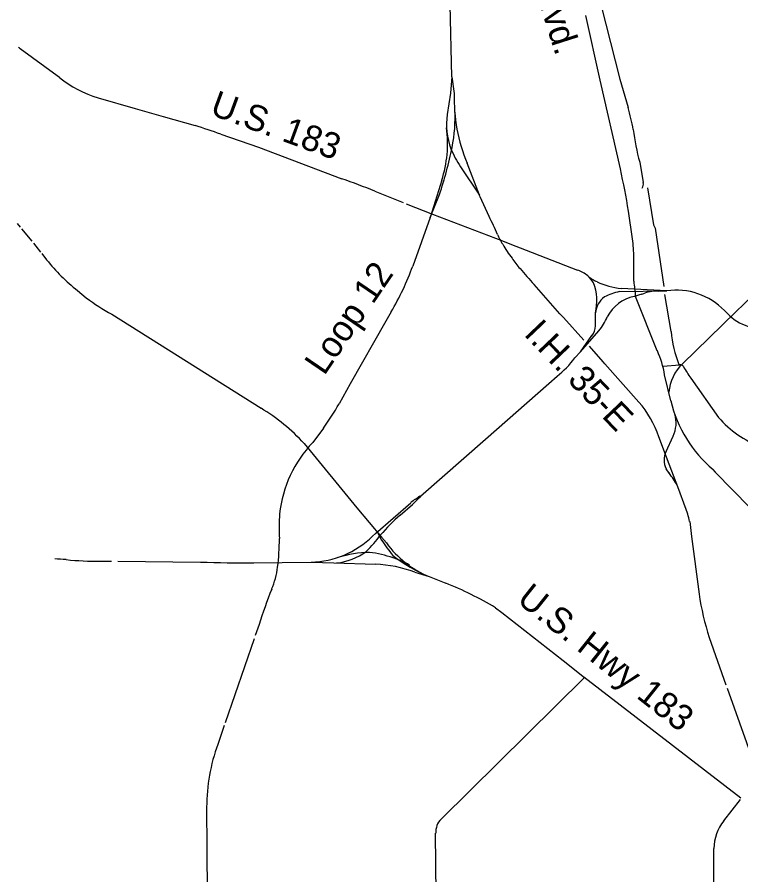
# Model space of a CAD drawing. Extents: x 105094 to 105814, y -291615 to -291123.
# Drawn here: x 105378.73 to 105412.75, y -291448.01 to -291407.68 of the extents above; entities that cross this region are included whole.
import ezdxf

# ---------------------------------------------------------------- set-up
doc = ezdxf.new("R2010")
doc.units = 0
doc.layers.add('G_MAP', color=7, linetype='Continuous')

msp = doc.modelspace()

# ---------------------------------------------------------------- linework, layer by layer
at = {"layer": 'G_MAP'}
for p, q in [((105399.162, -291410.487), (105399.094, -291407.102)), ((105406.14, -291410.645), (105405.459, -291407.609)), ((105380.615, -291410.448), (105378.874, -291409.172)), ((105380.715, -291410.515), (105380.615, -291410.448)), ((105399.162, -291410.487), (105399.1, -291411.252)), ((105399.162, -291410.487), (105399.278, -291411.278)), ((105407.093, -291414.817), (105406.14, -291410.645)), ((105407.067, -291410.6), (105407.448, -291411.928)), ((105399.1, -291411.252), (105398.951, -291412.254)), ((105382.533, -291411.481), (105384.283, -291411.975)), ((105384.283, -291411.975), (105385.595, -291412.356)), ((105385.595, -291412.356), (105387.096, -291412.779)), ((105388.307, -291413.183), (105390.083, -291413.797)), ((105390.083, -291413.797), (105394, -291415.279)), ((105400.461, -291416.053), (105399.885, -291414.547)), ((105407.997, -291414.501), (105408.166, -291415.456)), ((105399.575, -291414.714), (105400.461, -291416.053)), ((105398.693, -291415.351), (105398.147, -291417.101)), ((105395.547, -291415.86), (105396.884, -291416.397)), ((105398.147, -291417.101), (105398.584, -291416.02)), ((105400.498, -291416.132), (105400.424, -291415.974)), ((105400.921, -291417.052), (105400.498, -291416.132)), ((105397.026, -291416.451), (105398.26, -291416.939)), ((105398.305, -291416.642), (105398.276, -291416.755)), ((105398.147, -291417.101), (105397.328, -291419.382)), ((105398.26, -291416.939), (105401.544, -291418.199)), ((105407.658, -291418.097), (105407.474, -291416.8)), ((105378.932, -291417.63), (105379.429, -291418.215)), ((105379.503, -291418.305), (105379.829, -291418.731)), ((105401.544, -291418.199), (105401.977, -291418.367)), ((105401.977, -291418.367), (105402.374, -291418.528)), ((105402.374, -291418.528), (105405.072, -291419.571)), ((105379.888, -291418.796), (105380.117, -291419.09)), ((105407.722, -291420.097), (105407.722, -291418.995)), ((105414.633, -291419.497), (105412.511, -291421.538)), ((105404.25, -291421.622), (105403.03, -291420.253)), ((105381.57, -291420.533), (105381.983, -291420.876)), ((105408.09, -291420.698), (105407.732, -291420.814)), ((105408.09, -291420.698), (105408.242, -291420.656)), ((105408.899, -291420.559), (105409.266, -291420.55)), ((105409.482, -291422.462), (105409.178, -291420.718)), ((105408.826, -291423.372), (105407.806, -291420.808)), ((105396.31, -291421.541), (105396.057, -291421.967)), ((105412.511, -291421.538), (105410.007, -291423.975)), ((105412.107, -291421.603), (105411.984, -291421.476)), ((105383.175, -291421.644), (105390.195, -291426.069)), ((105404.418, -291421.8), (105404.25, -291421.622)), ((105405.364, -291422.875), (105404.418, -291421.8)), ((105405.917, -291422.198), (105405.917, -291421.586)), ((105396.057, -291421.967), (105394.381, -291424.926)), ((105405.209, -291423.418), (105406.082, -291422.428)), ((105405.209, -291423.418), (105405.753, -291422.656)), ((105406.278, -291423.883), (105405.636, -291423.153)), ((105404.941, -291423.702), (105405.209, -291423.418)), ((105406.365, -291423.98), (105406.278, -291423.883)), ((105407.954, -291425.782), (105406.365, -291423.98)), ((105409.088, -291424.083), (105409.885, -291424.027)), ((105403.72, -291424.906), (105404.111, -291424.561)), ((105409.459, -291425.721), (105409.168, -291424.496)), ((105410.407, -291424.661), (105411.707, -291426.505)), ((105394.381, -291424.926), (105393.864, -291425.858)), ((105400.743, -291427.529), (105403.72, -291424.906)), ((105393.126, -291427.007), (105392.627, -291427.684)), ((105397.691, -291430.199), (105400.743, -291427.529)), ((105409.255, -291428.365), (105408.89, -291427.416)), ((105409.242, -291428.104), (105409.566, -291427.388)), ((105392.23, -291427.729), (105394.707, -291430.758)), ((105409.83, -291429.886), (105409.255, -291428.365)), ((105409.376, -291429.113), (105409.235, -291428.91)), ((105411.429, -291428.95), (105411.542, -291429.072)), ((105411.548, -291429.072), (105413.182, -291430.736)), ((105410.139, -291430.703), (105409.83, -291429.886)), ((105394.707, -291430.758), (105395.859, -291432.131)), ((105395.575, -291431.95), (105397.245, -291430.509)), ((105396.735, -291431.097), (105397.319, -291430.597)), ((105410.347, -291431.391), (105410.431, -291432.105)), ((105395.436, -291432.083), (105395.575, -291431.95)), ((105395.652, -291431.884), (105395.86, -291432.265)), ((105396.095, -291432.402), (105395.859, -291432.131)), ((105410.431, -291432.105), (105410.789, -291434.802)), ((105382.644, -291433.251), (105383.161, -291433.264)), ((105383.458, -291433.264), (105387.346, -291433.303)), ((105389.859, -291433.332), (105391.19, -291433.322)), ((105391.19, -291433.322), (105392.552, -291433.303)), ((105392.552, -291433.303), (105393.618, -291433.338)), ((105393.618, -291433.338), (105395.571, -291433.403)), ((105397.425, -291433.782), (105398.094, -291433.981)), ((105398.094, -291433.981), (105398.879, -291434.294)), ((105398.094, -291433.981), (105398.094, -291433.981)), ((105401.217, -291435.447), (105401.514, -291435.67)), ((105401.514, -291435.67), (105404.404, -291437.934)), ((105390.101, -291436.242), (105389.923, -291436.755)), ((105411.264, -291436.852), (105412.045, -291439.071)), ((105389.872, -291436.913), (105388.509, -291440.86)), ((105404.404, -291437.934), (105405.408, -291438.725)), ((105398.658, -291445.382), (105405.408, -291438.725)), ((105405.364, -291438.69), (105412.752, -291444.38)), ((105412.11, -291439.229), (105413.598, -291443.414)), ((105388.467, -291440.976), (105388.17, -291441.871)), ((105411.945, -291445.464), (105412.739, -291444.47)), ((105387.64, -291444.826), (105387.653, -291446.773)), ((105398.378, -291446.05), (105398.426, -291449.919)), ((105387.653, -291446.773), (105387.662, -291449.127)), ((105411.486, -291450.371), (105411.489, -291446.767))]:
    msp.add_line(p, q, dxfattribs=at)
for points in [[(105401.98, -291391.62), (105403.902, -291398.822), (105405.317, -291403.953), (105406.186, -291407.151), (105407.067, -291410.6)], [(105408.371, -291415.712), (105408.652, -291417.44), (105408.717, -291417.605), (105409.133, -291420.343)], [(105378.731, -291417.39), (105378.874, -291417.559)], [(105407.041, -291420.58), (105409.266, -291420.55), (105407.125, -291420.431)]]:
    msp.add_lwpolyline(points, dxfattribs=at)
for centre, radius, start, end in [((105375.593, -291413.4), 5.352, 52.1891, 53.1979), ((105384.202, -291406.144), 5.592, 231.4185, 252.6325), ((105384.202, -291406.144), 5.592, 231.4185, 236.6344), ((105384.202, -291406.144), 5.592, 231.4185, 236.6344), ((105407.159, -291411.505), 7.884, 178.3488, 202.6951), ((105402.135, -291412.732), 3.22, 171.4532, 200.8371), ((105392.068, -291412.365), 7.253, 348.5591, 2.7437), ((105396.593, -291415.044), 11.293, 10.6155, 16.0174), ((105375.489, -291449.616), 38.622, 70.6165, 72.5103), ((105393.394, -291413.623), 5.573, 341.9407, 7.5303), ((105418.424, -291411.644), 10.812, 187.0103, 195.3212), ((105380.707, -291410.046), 18.849, 341.5211, 348.5006), ((105403.215, -291412.222), 4.412, 202.0405, 214.3927), ((105355.548, -291425.747), 52.691, 9.7758, 11.9715), ((105374.509, -291469.492), 57.611, 68.58133, 70.22483), ((105407.82, -291415.518), 0.352, 324.5634, 10.0772), ((105383.889, -291425.363), 18.952, 23.1971, 26.0109), ((105405.508, -291415.918), 4.643, 205.2441, 211.6842), ((105401.377, -291418.995), 6.345, 0, 8.1433), ((105406.669, -291415.443), 5.884, 209.6859, 217.4277), ((105387.141, -291413.472), 8.994, 218.6499, 231.7267), ((105407.663, -291415.024), 6.933, 215.1813, 220.2433), ((105385.541, -291415.148), 12.524, 329.3029, 340.2417), ((105416.676, -291407.59), 18.616, 219.7865, 222.8574), ((105404.35, -291421.437), 2.001, 52.8434, 68.8502), ((105406.485, -291418.848), 1.359, 227.0095, 248.9762), ((105403.959, -291421.436), 2.258, 34.0465, 44.8921), ((105403.551, -291421.022), 2.432, 346.586, 20.4612), ((105407.352, -291417.435), 3.005, 243.2062, 265.6713), ((105414.706, -291419.633), 6.999, 183.7973, 189.6619), ((105407.734, -291423.629), 3.124, 102.7718, 116.5801), ((105408.881, -291422.701), 2.142, 89.5255, 107.3688), ((105409.721, -291423.666), 3.149, 44.0508, 98.3079), ((105387.373, -291413.828), 8.873, 232.5934, 241.7598), ((105406.999, -291421.698), 1.088, 127.5025, 174.0869), ((105408.106, -291422.611), 1.835, 101.7471, 152.8774), ((105404.15, -291420.831), 2.506, 320.4149, 337.893), ((105413.837, -291419.928), 2.408, 224.0757, 280.0497), ((105405.193, -291422.198), 0.724, 320.7494, 359.9907), ((105414.435, -291422.124), 4.965, 183.9054, 202.3534), ((105404.72, -291425.237), 4.51, 9.4521, 24.4201), ((105401.769, -291421.467), 3.881, 307.13, 324.8372), ((105411.484, -291425.5), 2.123, 134.0704, 175.1339), ((105409.9, -291424.2), 0.174, 30.8362, 94.9544), ((105417.471, -291419.682), 8.643, 210.8276, 215.1777), ((105384.596, -291420.717), 10.598, 323.5944, 330.9878), ((105404.661, -291428.754), 4.436, 17.5591, 42.0701), ((105415.348, -291424.324), 6.053, 193.3476, 229.8421), ((105385.454, -291433.956), 9.202, 42.5857, 58.9897), ((105408.256, -291426.761), 1.452, 334.4515, 16.7633), ((105415.353, -291423.359), 4.816, 220.7835, 249.7495), ((105396.717, -291431.622), 5.678, 136.0849, 174.009), ((105410.044, -291428.514), 0.9, 152.8813, 206.0913), ((105406.527, -291431.406), 3.657, 27.6625, 38.8428), ((105398.914, -291432.507), 2.61, 123.961, 129.9353), ((105395.634, -291428.589), 2.61, 309.9353, 315.9095), ((105395.998, -291428.178), 2.61, 303.9611, 309.9353), ((105399.383, -291432.221), 2.61, 129.9353, 135.9095), ((105405.163, -291432.582), 5.318, 12.9345, 20.6861), ((105400.57, -291431.693), 9.523, 176.0031, 183.0414), ((105401.953, -291437.185), 8.018, 130.5991, 139.9635), ((105392.616, -291429.878), 3.853, 310.7779, 326.0994), ((105380.615, -291432.216), 10.446, 352.7262, 0.0969), ((105392.455, -291429.055), 4.249, 271.3119, 314.5524), ((105404.885, -291426.249), 10.845, 213.6858, 218.403), ((105399.879, -291429.667), 4.669, 215.8587, 247.521), ((105393.52, -291430.717), 2.631, 274.8797, 307.7986), ((105378.636, -291467.715), 34.615, 86.0293, 86.912), ((105382.341, -291421.293), 11.962, 263.7235, 271.4552), ((105395.491, -291438.829), 5.988, 91.8873, 106.2687), ((105394.552, -291438.554), 5.757, 71.223, 82.5923), ((105401.148, -291426.772), 7.829, 232.5366, 247.0418), ((105395.167, -291437.021), 4.109, 60.6707, 72.4689), ((105389.309, -291372.311), 61.023, 268.15672, 270.51607), ((105387.231, -291433.085), 3.772, 336.6693, 353.0863), ((105395.368, -291439.125), 5.725, 68.9387, 87.9645), ((105393.021, -291449.12), 15.941, 59.0608, 68.441), ((105416.018, -291444.565), 27.22, 158.4771, 162.1953), ((105424.257, -291432.765), 13.621, 188.6002, 197.4633), ((105396.006, -291444.8), 8.366, 159.5002, 180.1728), ((105399.235, -291445.964), 0.82, 134.7184, 185.9923), ((105413.586, -291446.769), 2.097, 141.4976, 179.9405)]:
    msp.add_arc(centre, radius, start, end, dxfattribs=at)

# ---------------------------------------------------------------- texts
for s, height, rotation, p in [('Harry Hines Blvd.', 1.21107, 287.6712, (105400.24, -291397.539)), ('U.S. 183', 1.2111, 339.8934, (105387.744, -291412.243)), ('Loop 12', 1.2111, 55.7349, (105393.167, -291424.57)), ('I.H. 35-E', 1.2111, 313.6181, (105402.511, -291422.614)), ('U.S. Hwy 183', 1.21107, 321.4486, (105402.167, -291435.161))]:
    msp.add_text(s, height=height, rotation=rotation, dxfattribs=at).set_placement(p)

doc.saveas('drawing.dxf')
